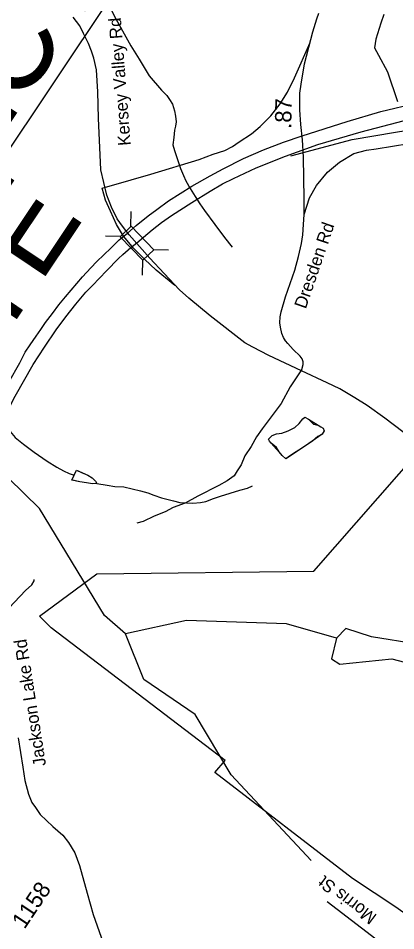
# Model space of a CAD drawing. Extents: x 1715610 to 1720914, y 798298 to 802505.
# Drawn here: x 1716054.7 to 1716117.1, y 799554.8 to 799705.3 of the extents above; entities that cross this region are included whole.
import ezdxf

# ---------------------------------------------------------------- set-up
doc = ezdxf.new("R2010")
doc.units = 0
doc.layers.add('Default', color=7, linetype='Continuous')
doc.layers.add('Prop DSN Text', color=7, linetype='Continuous')

msp = doc.modelspace()

# ---------------------------------------------------------------- linework, layer by layer
at = {"layer": 'Default'}
for p, q in [((1716073.31, 799671), (1716073.37, 799673.46)), ((1716071.54, 799669.3), (1716069.08, 799669.35)), ((1716079.54, 799667.09), (1716077.08, 799667.14)), ((1716075.21, 799662.94), (1716075.26, 799665.4))]:
    msp.add_line(p, q, dxfattribs=at)
for points in [[(1716101.48, 799647.15), (1716096.11, 799649.68), (1716093.42, 799651.07), (1716092.14, 799651.78), (1716086.37, 799656.24), (1716082.9, 799659.13), (1716081.35, 799660.52), (1716078.81, 799663.19), (1716076.43, 799665.75), (1716072.99, 799669.61), (1716071.9, 799671.05), (1716071.01, 799672.23), (1716070.12, 799674.17), (1716069.31, 799676.13), (1716068.33, 799680.31), (1716067.96, 799688.84), (1716067.82, 799693.2), (1716067.6, 799696.83), (1716067.18, 799698.75), (1716066.82, 799699.89), (1716066.32, 799701.18), (1716065.48, 799702.79), (1716064.85, 799704.09), (1716063.79, 799705.5)], [(1716070.1, 799706.62), (1716070.79, 799705.25), (1716073.29, 799700.8), (1716074.65, 799698.55), (1716076.32, 799695.83), (1716078.34, 799693.46), (1716079.22, 799692.59), (1716079.68, 799691.95), (1716080.2, 799691.18), (1716080.51, 799690.08), (1716080.68, 799689.17), (1716080.79, 799688.25), (1716080.65, 799687.5), (1716080.52, 799686.85), (1716080.37, 799685.63), (1716080.25, 799684.45), (1716080.51, 799683.53), (1716081.48, 799680.56), (1716081.99, 799679.36), (1716082.37, 799678.53), (1716083.08, 799677.25), (1716083.92, 799675.94), (1716084.71, 799674.71), (1716085.45, 799673.63), (1716087.17, 799671.29), (1716088.76, 799669.15), (1716090.04, 799667.54)], [(1716101.48, 799647.15), (1716101.74, 799648.19), (1716101.75, 799648.65), (1716101.57, 799649.11), (1716101.28, 799649.6), (1716100.12, 799650.7), (1716099.21, 799651.65), (1716098.85, 799652.08), (1716098.52, 799652.64), (1716098.21, 799653.32), (1716098.02, 799654.35), (1716097.93, 799655.08), (1716097.95, 799656.05), (1716098.1, 799656.91), (1716098.86, 799659.36), (1716100.37, 799663.75), (1716100.99, 799666.02), (1716101.48, 799668.14), (1716101.69, 799669.6), (1716101.83, 799671.28), (1716101.9, 799672.97), (1716101.9, 799675.56), (1716101.83, 799682.4), (1716101.63, 799685.28), (1716101.35, 799687.82), (1716101.2, 799690.24), (1716101.23, 799692.97), (1716101.42, 799694.48), (1716102, 799697.83), (1716103.38, 799703.1), (1716104.01, 799705.21), (1716104.37, 799706.14)], [(1716115.11, 799705.97), (1716114.61, 799704.49), (1716113.78, 799701.9), (1716113.57, 799700.43), (1716114.23, 799699.22), (1716115.69, 799696.5), (1716117.37, 799691.6)], [(1716068.58, 799677.27), (1716073.32, 799678.65), (1716076.6, 799679.63), (1716084.56, 799682.03), (1716086.91, 799682.89), (1716088.83, 799683.53), (1716090.07, 799684.19), (1716091.2, 799684.92), (1716093.25, 799686.28), (1716094.64, 799687.48), (1716096.41, 799689.22), (1716097.94, 799691.22), (1716099.17, 799693.12), (1716100.32, 799695.52), (1716102.92, 799701.32)], [(1716101.57, 799685.93), (1716109.05, 799688.29), (1716114.59, 799689.95), (1716120.57, 799691.4), (1716124.5, 799692.36), (1716133.28, 799694.16), (1716137.8, 799694.95), (1716142.39, 799695.67), (1716149.08, 799696.51), (1716155.15, 799697.24), (1716159.55, 799697.58), (1716162.59, 799697.76)], [(1716074.26, 799668.3), (1716076.8, 799670.4), (1716078.37, 799671.63), (1716080, 799672.79), (1716083.36, 799674.94), (1716086.42, 799676.78), (1716088.43, 799677.99), (1716090.24, 799678.91), (1716093.97, 799680.67), (1716098.85, 799682.6), (1716104.16, 799684.48), (1716111.35, 799686.6), (1716120.84, 799689.04), (1716133.27, 799691.71), (1716139.34, 799692.84)], [(1716099.73, 799682.62), (1716109.87, 799685.31), (1716116.99, 799686.56), (1716121.47, 799687.23), (1716123.87, 799687.51), (1716126.89, 799687.69), (1716134.16, 799687.62), (1716139.17, 799687.29), (1716140.28, 799687.25)], [(1716072.76, 799669.88), (1716074.15, 799671.12), (1716076.18, 799672.72), (1716077.61, 799673.8), (1716079.52, 799675.19), (1716083.37, 799677.63), (1716086.38, 799679.34), (1716088.57, 799680.49), (1716091.92, 799682.19), (1716095.23, 799683.61), (1716098.53, 799684.91), (1716101.57, 799685.93)], [(1716101.9, 799672.97), (1716102.79, 799675.7), (1716103.99, 799677.71), (1716105.78, 799679.93), (1716107.78, 799681.56), (1716110.13, 799683.02), (1716112.25, 799683.58), (1716113.84, 799683.8), (1716119.22, 799684.69), (1716125.11, 799685.08), (1716128.32, 799685.21), (1716130.98, 799685.33), (1716132.99, 799685.27), (1716134.48, 799685.11), (1716136.21, 799684.87), (1716138.14, 799684.11), (1716139.56, 799683.39), (1716141.53, 799682.14), (1716142.88, 799680.86), (1716144.54, 799678.91)], [(1716072.07, 799669.38), (1716070.95, 799671.32), (1716069.92, 799673.49), (1716069.09, 799675.29), (1716068.58, 799677.27)], [(1716053.15, 799645.31), (1716054.95, 799648.5), (1716055.86, 799650.25), (1716056.68, 799651.46), (1716057.64, 799652.85), (1716058.41, 799654), (1716059.18, 799655.13), (1716060.33, 799656.64), (1716061.41, 799658.05), (1716062.49, 799659.37), (1716065.32, 799662.68), (1716066.7, 799664.13), (1716067.7, 799665.2), (1716069.98, 799667.41), (1716071.36, 799668.75), (1716072.76, 799669.88)], [(1716080.58, 799661.21), (1716077.49, 799663.77), (1716075.56, 799665.56), (1716073.74, 799667.42), (1716072.42, 799669), (1716072.07, 799669.38)], [(1716036.89, 799610.04), (1716039.32, 799614.69), (1716043.63, 799622.97), (1716044.75, 799625.01), (1716051.48, 799637.87), (1716054.16, 799642.95), (1716057.17, 799648.22), (1716059.03, 799651.06), (1716060.98, 799653.91), (1716062.54, 799656.07), (1716064.21, 799658.15), (1716065.88, 799660.11), (1716066.95, 799661.23), (1716069.27, 799663.67), (1716071.26, 799665.7), (1716071.99, 799666.34), (1716073.29, 799667.48), (1716074.26, 799668.3)], [(1716101.39, 799647.16), (1716099.63, 799644.54), (1716098.14, 799641.75), (1716094.99, 799637.61), (1716094.06, 799636.29), (1716093.15, 799634.68), (1716092.12, 799633.11), (1716091.53, 799631.65), (1716090.88, 799630.68), (1716090.38, 799629.81), (1716089.23, 799628.99), (1716087.84, 799628.21), (1716084.38, 799626.49), (1716082.26, 799625.34), (1716080.29, 799624.59), (1716078.95, 799623.88), (1716077.12, 799623.15), (1716075.33, 799622.28), (1716074.28, 799622)], [(1716119.81, 799635.89), (1716115.25, 799639.33), (1716112.32, 799641.41), (1716110.31, 799642.7), (1716107.8, 799644.19), (1716105.75, 799645.18), (1716101.48, 799647.15)], [(1716096.01, 799635.86), (1716096.64, 799636.48), (1716097.37, 799636.77), (1716098.22, 799636.87), (1716099.31, 799637.23), (1716100.4, 799637.81), (1716101.12, 799638.48), (1716101.69, 799639.24), (1716102.05, 799639.53), (1716102.64, 799639.17), (1716103.18, 799638.65), (1716103.45, 799638.35), (1716104.24, 799638.19), (1716104.69, 799637.93), (1716105.05, 799637.68), (1716105.25, 799637.28), (1716104.92, 799636.72), (1716104.18, 799636.33), (1716103.29, 799635.57), (1716102.16, 799634.76), (1716101.04, 799634.05), (1716100.34, 799633.63), (1716099.53, 799633.08), (1716098.9, 799632.61), (1716098.29, 799633.18), (1716097.8, 799633.78), (1716097.33, 799634.48), (1716096.5, 799635.2), (1716096.22, 799635.55), (1716096.01, 799635.86)], [(1716096.01, 799635.86), (1716096.64, 799636.48), (1716097.37, 799636.77), (1716098.22, 799636.87), (1716099.31, 799637.23), (1716100.4, 799637.81), (1716101.12, 799638.48), (1716101.69, 799639.24), (1716102.05, 799639.53), (1716102.64, 799639.17), (1716104.69, 799637.93), (1716105.05, 799637.68), (1716105.25, 799637.28), (1716104.92, 799636.72), (1716102.16, 799634.76), (1716098.9, 799632.61), (1716098.29, 799633.18), (1716096.5, 799635.2), (1716096.22, 799635.55), (1716096.01, 799635.86)], [(1716051.83, 799637.68), (1716052.72, 799637.6), (1716053.34, 799637.12), (1716054.21, 799636.16), (1716055.55, 799635.03), (1716057.3, 799633.74), (1716059.46, 799632.26), (1716061.05, 799631.28), (1716062.17, 799630.67), (1716063.1, 799630.19), (1716063.93, 799629.94)], [(1716135.5, 799521.82), (1716119.76, 799533.88), (1716120.92, 799540.98), (1716120.2, 799542.66), (1716116.17, 799545.47), (1716118, 799548.07), (1716114.99, 799550.42), (1716119.52, 799551.92), (1716123.32, 799553.42), (1716119.54, 799556.9), (1716117.06, 799558.69), (1716109.93, 799563.38), (1716087.19, 799580.88), (1716088.88, 799582.87), (1716060.14, 799604.73), (1716058.21, 799606.69), (1716067.68, 799613.64), (1716103.5, 799614.09), (1716121.16, 799634.15)], [(1716135.5, 799521.82), (1716119.76, 799533.88), (1716120.92, 799540.98), (1716120.2, 799542.66), (1716116.17, 799545.47), (1716118, 799548.07), (1716114.99, 799550.42), (1716119.52, 799551.92), (1716123.32, 799553.42), (1716119.54, 799556.9), (1716117.06, 799558.69), (1716109.93, 799563.38), (1716087.19, 799580.88), (1716088.88, 799582.87), (1716060.14, 799604.73), (1716058.21, 799606.69), (1716067.68, 799613.64), (1716103.5, 799614.09), (1716121.16, 799634.15)], [(1716072.43, 799603.78), (1716068.96, 799606.8), (1716058.23, 799624.46), (1716050.43, 799631.98)], [(1716063.93, 799629.94), (1716064.34, 799630.77), (1716065.13, 799630.39), (1716066.19, 799629.93), (1716066.9, 799629.5), (1716067.47, 799628.95), (1716067.67, 799628.54)], [(1716063.93, 799629.94), (1716064.34, 799630.77), (1716066.19, 799629.93), (1716066.9, 799629.5), (1716067.47, 799628.95), (1716067.67, 799628.54)], [(1716067.67, 799628.54), (1716066.96, 799628.51), (1716065.96, 799628.66), (1716064.86, 799628.83), (1716063.91, 799629.06), (1716063.56, 799629.09), (1716063.93, 799629.94)], [(1716067.67, 799628.54), (1716066.96, 799628.51), (1716065.96, 799628.66), (1716064.86, 799628.83), (1716063.56, 799629.09), (1716063.93, 799629.94)], [(1716067.67, 799628.54), (1716069.38, 799628.28), (1716070.67, 799628.08), (1716072.12, 799628.04), (1716074.87, 799627.37), (1716076.1, 799627.01), (1716077.07, 799626.65), (1716078.35, 799626.21), (1716080.36, 799625.68), (1716081.41, 799625.44), (1716083.55, 799625.34), (1716084.78, 799625.45), (1716085.69, 799625.62), (1716086.95, 799626.07), (1716088.1, 799626.45), (1716091.32, 799627.46), (1716092.55, 799627.79), (1716093.41, 799628.2)], [(1716049.1, 799603.8), (1716049.53, 799604.29), (1716050.36, 799605.14), (1716055.9, 799610.91), (1716056.92, 799611.83), (1716057.3, 799612.51), (1716057.32, 799612.7)], [(1716107.27, 799603.05), (1716098.99, 799605.4), (1716082.47, 799605.94), (1716072.43, 799603.78)], [(1716107.27, 799603.05), (1716106.46, 799599.64), (1716107.82, 799598.73), (1716116.4, 799599.66), (1716124.33, 799597.55), (1716125.14, 799598.96), (1716120.6, 799602.06), (1716113.07, 799603.25), (1716108.81, 799604.63), (1716107.27, 799603.05)], [(1716103.07, 799566.39), (1716089.84, 799580.48), (1716083.92, 799590.46), (1716075.43, 799596.25), (1716072.43, 799603.78)], [(1716054.67, 799586.59), (1716055.43, 799581.78), (1716055.76, 799579.54), (1716056.36, 799577.31), (1716056.94, 799575.95), (1716057.52, 799575.11), (1716058.34, 799573.98), (1716060.42, 799571.98), (1716062.05, 799570.57), (1716062.97, 799569.32), (1716064.06, 799567.64), (1716064.82, 799565.56), (1716066.06, 799561), (1716067.06, 799557.48), (1716068.7, 799552.78), (1716071.13, 799546.44), (1716074.79, 799536.65), (1716076.89, 799532.76), (1716079.06, 799529.74), (1716080.59, 799528.32), (1716086.92, 799523.74)], [(1716115.47, 799551.44), (1716115.41, 799552.14), (1716105.72, 799559.54)]]:
    msp.add_lwpolyline(points, dxfattribs=at)
msp.add_lwpolyline([(1716075.26, 799665.4), (1716071.53, 799669.29), (1716073.35, 799671.03), (1716077.08, 799667.14)], close=True, dxfattribs=at)
at = {"layer": 'Prop DSN Text'}
msp.add_line((1716020.09, 799634.2), (1716073.54, 799714.06), dxfattribs=at)

# ---------------------------------------------------------------- texts
at = {"layer": 'Default'}
for s, height, rotation, p in [('Kersey Valley Rd', 2.0663, 94.4036, (1716073.28, 799684.37)), ('.87', 2.719, 89.2996, (1716099.81, 799687.07)), ('Dresden Rd', 2.066, 71.123, (1716102.19, 799657.27)), ('Jackson Lake Rd', 2.0663, 98.9245, (1716059.3, 799582.08)), ('Morris St', 2.066, 142.8194, (1716114.07, 799557.31)), ('1158', 2.719, 56.2051, (1716055.73, 799554.93))]:
    msp.add_text(s, height=height, rotation=rotation, dxfattribs=at).set_placement(p)
at = {"layer": 'Prop DSN Text'}
for s, p in [('PROJECT ', (1716018.55, 799635.97)), ('SITE', (1716041.3, 799636.02))]:
    msp.add_text(s, height=14.701, rotation=56.2051, dxfattribs=at).set_placement(p)

doc.saveas('drawing.dxf')
